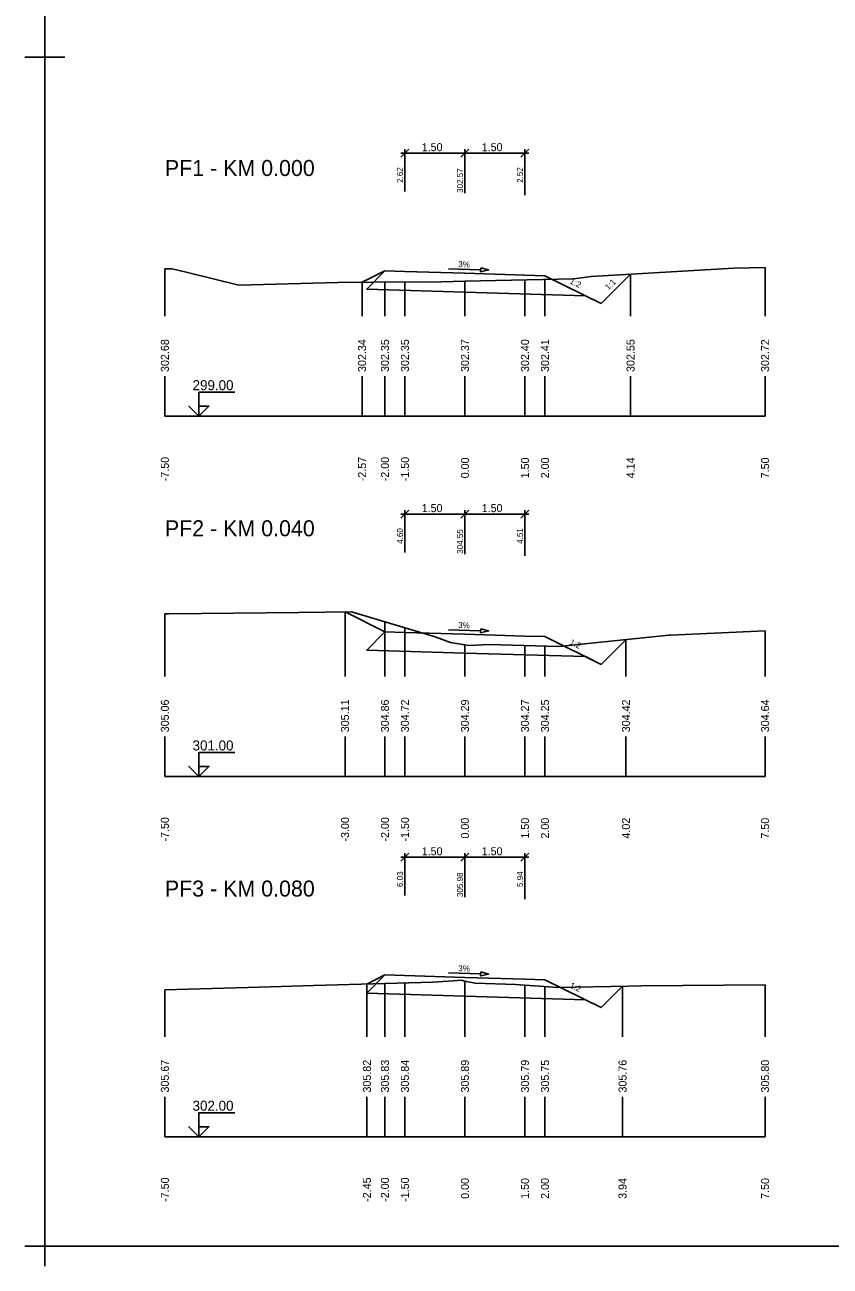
# Model space of a CAD drawing. Extents: x -5 to 1265, y -2 to 602.
# Drawn here: x -5 to 196.3, y -2.3 to 307.8 of the extents above; entities that cross this region are included whole.
import ezdxf

# ---------------------------------------------------------------- set-up
doc = ezdxf.new("R2010")
doc.units = 0
for name, color, linetype in [('KOTA', 7, 'Continuous'), ('KOTA_DELKY', 7, 'Continuous'), ('KOTA_DELKY_CONT', 7, 'Continuous'), ('NS_TELESO_VOZOVKY', 7, 'Continuous'), ('NS_V_PF', 7, 'Continuous'), ('REZY_PF_PUVODNI', 7, 'Continuous'), ('SESTAVY_REZU_PF', 7, 'Continuous'), ('SKLON', 7, 'Continuous'), ('SVK', 7, 'Continuous')]:
    doc.layers.add(name, color=color, linetype=linetype)

msp = doc.modelspace()

# ---------------------------------------------------------------- linework, layer by layer
for p, q in [((0, 304.67), (0, 294.67)), ((0, 304.67), (0, 294.67)), ((0, 304.67), (0, 294.67)), ((0, 304.67), (0, 294.67)), ((0, 304.67), (0, 294.67)), ((0, 304.67), (0, 294.67)), ((0, 304.67), (0, 294.67)), ((0, 304.67), (0, 294.67)), ((0, 304.67), (0, 294.67)), ((0, 304.67), (0, 294.67)), ((0, 304.67), (0, 294.67)), ((0, 304.67), (0, 294.67)), ((0, 304.67), (0, 294.67)), ((0, 304.67), (0, 294.67)), ((0, 304.67), (0, 294.67)), ((0, 304.67), (0, 294.67)), ((0, 304.67), (0, 294.67)), ((0, 304.67), (0, 294.67)), ((0, 304.67), (0, 294.67)), ((0, 304.67), (0, 294.67)), ((0, 304.67), (0, 294.67)), ((0, 304.67), (0, 294.67)), ((0, 304.67), (0, 294.67)), ((0, 304.67), (0, 294.67)), ((0, 304.67), (0, 294.67)), ((0, 304.67), (0, 294.67)), ((0, 304.67), (0, 294.67)), ((0, 304.67), (0, 294.67)), ((0, 304.67), (0, 294.67)), ((0, 304.67), (0, 294.67)), ((0, 304.67), (0, 294.67)), ((0, 304.67), (0, 294.67)), ((0, 304.67), (0, 294.67)), ((0, 304.67), (0, 294.67)), ((0, 304.67), (0, 294.67)), ((0, 304.67), (0, 294.67)), ((0, 304.67), (0, 294.67)), ((0, 304.67), (0, 294.67)), ((0, 304.67), (0, 294.67)), ((0, 304.67), (0, 294.67)), ((0, 304.67), (0, 294.67)), ((0, 304.67), (0, 294.67)), ((0, 304.67), (0, 294.67)), ((0, 304.67), (0, 294.67)), ((5, 299.67), (-5, 299.67)), ((5, 299.67), (-5, 299.67)), ((5, 299.67), (-5, 299.67)), ((5, 299.67), (-5, 299.67)), ((5, 299.67), (-5, 299.67)), ((5, 299.67), (-5, 299.67)), ((5, 299.67), (-5, 299.67)), ((5, 299.67), (-5, 299.67)), ((5, 299.67), (-5, 299.67)), ((5, 299.67), (-5, 299.67)), ((5, 299.67), (-5, 299.67)), ((5, 299.67), (-5, 299.67)), ((5, 299.67), (-5, 299.67)), ((5, 299.67), (-5, 299.67)), ((5, 299.67), (-5, 299.67)), ((5, 299.67), (-5, 299.67)), ((5, 299.67), (-5, 299.67)), ((5, 299.67), (-5, 299.67)), ((5, 299.67), (-5, 299.67)), ((5, 299.67), (-5, 299.67)), ((5, 299.67), (-5, 299.67)), ((5, 299.67), (-5, 299.67)), ((5, 299.67), (-5, 299.67)), ((5, 299.67), (-5, 299.67)), ((5, 299.67), (-5, 299.67)), ((5, 299.67), (-5, 299.67)), ((5, 299.67), (-5, 299.67)), ((5, 299.67), (-5, 299.67)), ((5, 299.67), (-5, 299.67)), ((5, 299.67), (-5, 299.67)), ((5, 299.67), (-5, 299.67)), ((5, 299.67), (-5, 299.67)), ((5, 299.67), (-5, 299.67)), ((5, 299.67), (-5, 299.67)), ((5, 299.67), (-5, 299.67)), ((5, 299.67), (-5, 299.67)), ((5, 299.67), (-5, 299.67)), ((5, 299.67), (-5, 299.67)), ((5, 299.67), (-5, 299.67)), ((5, 299.67), (-5, 299.67)), ((5, 299.67), (-5, 299.67)), ((5, 299.67), (-5, 299.67)), ((5, 299.67), (-5, 299.67)), ((5, 299.67), (-5, 299.67)), ((0, 7.67), (0, -2.33)), ((0, 7.67), (0, -2.33)), ((0, 7.67), (0, -2.33)), ((0, 7.67), (0, -2.33)), ((0, 7.67), (0, -2.33)), ((0, 7.67), (0, -2.33)), ((0, 7.67), (0, -2.33)), ((0, 7.67), (0, -2.33)), ((5, 2.67), (-5, 2.67)), ((5, 2.67), (-5, 2.67)), ((5, 2.67), (-5, 2.67)), ((5, 2.67), (-5, 2.67)), ((5, 2.67), (-5, 2.67)), ((5, 2.67), (-5, 2.67)), ((5, 2.67), (-5, 2.67)), ((5, 2.67), (-5, 2.67))]:
    msp.add_line(p, q)
msp.add_lwpolyline([(0, 596.67), (1260, 596.67), (1260, 2.67), (0, 2.67)], close=True)
at = {"layer": 'KOTA'}
for points in [[(38.51, 210), (36.01, 212.5), (38.51, 210), (38.51, 216), (47.51, 216)], [(38.51, 210), (41.01, 212.5), (38.51, 212.5), (38.51, 210)], [(38.51, 210), (41.01, 212.5), (38.51, 212.5)], [(38.51, 120), (36.01, 122.5), (38.51, 120), (38.51, 126), (47.51, 126)], [(38.51, 120), (41.01, 122.5), (38.51, 122.5), (38.51, 120)], [(38.51, 120), (41.01, 122.5), (38.51, 122.5)], [(38.51, 30), (36.01, 32.5), (38.51, 30), (38.51, 36), (47.51, 36)], [(38.51, 30), (41.01, 32.5), (38.51, 32.5), (38.51, 30)], [(38.51, 30), (41.01, 32.5), (38.51, 32.5)]]:
    msp.add_lwpolyline(points, dxfattribs=at)
at = {"layer": 'KOTA_DELKY'}
for points in [[(89, 274.7), (91, 276.7)], [(90, 266.15), (90, 276.7)], [(104, 274.7), (106, 276.7)], [(104, 274.7), (106, 276.7)], [(105, 265.7), (105, 276.7)], [(105, 265.7), (105, 276.7)], [(119, 274.7), (121, 276.7)], [(120, 265.25), (120, 276.7)], [(89, 275.7), (106, 275.7)], [(104, 275.7), (121, 275.7)], [(89, 184.54), (91, 186.54)], [(90, 175.99), (90, 186.54)], [(104, 184.54), (106, 186.54)], [(104, 184.54), (106, 186.54)], [(105, 175.54), (105, 186.54)], [(105, 175.54), (105, 186.54)], [(119, 184.54), (121, 186.54)], [(120, 175.09), (120, 186.54)], [(89, 185.54), (106, 185.54)], [(104, 185.54), (121, 185.54)], [(89, 98.81), (91, 100.81)], [(89, 99.81), (106, 99.81)], [(90, 90.26), (90, 100.81)], [(104, 98.81), (106, 100.81)], [(104, 98.81), (106, 100.81)], [(104, 99.81), (121, 99.81)], [(105, 89.81), (105, 100.81)], [(105, 89.81), (105, 100.81)], [(119, 98.81), (121, 100.81)], [(120, 89.36), (120, 100.81)]]:
    msp.add_lwpolyline(points, dxfattribs=at)
at = {"layer": 'NS_TELESO_VOZOVKY'}
for points in [[(105, 245.7), (120, 245.25), (125, 245.1), (139.01, 238.17), (135.11, 240.1), (105, 241), (80.44, 241.74), (85, 246.3), (90, 246.15), (105, 245.7)], [(105, 155.54), (120, 155.09), (125, 154.94), (139.01, 148.01), (135.11, 149.94), (105, 150.84), (80.44, 151.58), (85, 156.14), (90, 155.99), (105, 155.54)], [(105, 69.81), (120, 69.36), (125, 69.21), (139.01, 62.27), (135.11, 64.2), (105, 65.11), (80.44, 65.84), (85, 70.41), (90, 70.26), (105, 69.81)]]:
    msp.add_lwpolyline(points, dxfattribs=at)
at = {"layer": 'NS_V_PF'}
for points in [[(79.28, 243.44), (85, 246.3), (90, 246.15), (105, 245.7), (120, 245.25), (125, 245.1), (139.01, 238.17), (146.38, 245.46)], [(75.02, 161.13), (85, 156.14), (90, 155.99), (105, 155.54), (120, 155.09), (125, 154.94), (139.01, 148.01), (145.24, 154.17)], [(80.49, 68.15), (85, 70.41), (90, 70.26), (105, 69.81), (120, 69.36), (125, 69.21), (139.01, 62.27), (144.38, 67.59)]]:
    msp.add_lwpolyline(points, dxfattribs=at)
at = {"layer": 'REZY_PF_PUVODNI'}
for points in [[(30, 246.81), (31.76, 246.8), (33.2, 246.47), (35.63, 245.9), (48.46, 242.76), (73.22, 243.39), (81.88, 243.46), (99.16, 243.57), (105, 243.7), (132.21, 244.31), (136.52, 244.88), (172.17, 246.98), (180, 247.15)], [(30, 160.59), (30.98, 160.61), (63.51, 161), (76.61, 161.15), (97.54, 154.91), (101.42, 153.45), (105, 152.89), (105, 152.89), (106.01, 152.73), (111.08, 152.98), (128.42, 152.43), (155.93, 155.28), (156.34, 155.32), (180, 156.36)], [(30, 66.71), (53.63, 67.4), (67.13, 67.78), (96.93, 68.61), (102.08, 68.97), (104.02, 69.11), (105, 68.9), (105, 68.9), (107.58, 68.33), (117.66, 68.06), (128.18, 67.26), (145.91, 67.62), (149.16, 67.66), (180, 67.99)]]:
    msp.add_lwpolyline(points, dxfattribs=at)
at = {"layer": 'SESTAVY_REZU_PF'}
for points in [[(30, 210), (180, 210)], [(30, 120), (180, 120)], [(30, 30), (180, 30)]]:
    msp.add_lwpolyline(points, dxfattribs=at)
at = {"layer": 'SKLON'}
for points in [[(100.92, 246.82), (108.91, 246.58)], [(108.93, 247.08), (110.91, 246.52), (108.9, 246.08), (108.93, 247.08)], [(100.92, 156.66), (108.91, 156.42)], [(108.93, 156.92), (110.91, 156.36), (108.9, 155.92), (108.93, 156.92)], [(100.92, 70.93), (108.91, 70.69)], [(108.93, 71.19), (110.91, 70.63), (108.9, 70.19), (108.93, 71.19)]]:
    msp.add_lwpolyline(points, dxfattribs=at)
for points in [[(108.93, 247.08), (110.91, 246.52), (108.9, 246.08)], [(108.93, 156.92), (110.91, 156.36), (108.9, 155.92)], [(108.93, 71.19), (110.91, 70.63), (108.9, 70.19)]]:
    msp.add_lwpolyline(points, close=True, dxfattribs=at)
at = {"layer": 'SVK'}
for points in [[(30, 235), (30, 246.81)], [(146.38, 235), (146.38, 245.46)], [(180, 235), (180, 247.15)], [(79.28, 235), (79.28, 243.44)], [(85, 235), (85, 243.48)], [(90, 235), (90, 243.51)], [(105, 235), (105, 243.7)], [(120, 235), (120, 244.04)], [(125, 235), (125, 244.15)], [(30, 210), (30, 220)], [(79.28, 210), (79.28, 220)], [(85, 210), (85, 220)], [(90, 210), (90, 220)], [(105, 210), (105, 220)], [(120, 210), (120, 220)], [(125, 210), (125, 220)], [(146.38, 210), (146.38, 220)], [(180, 210), (180, 220)], [(30, 145), (30, 160.59)], [(75.02, 145), (75.02, 161.13)], [(85, 145), (85, 158.65)], [(90, 145), (90, 157.16)], [(180, 145), (180, 156.36)], [(105, 145), (105, 152.89)], [(120, 145), (120, 152.69)], [(125, 145), (125, 152.54)], [(145.24, 145), (145.24, 154.17)], [(30, 120), (30, 130)], [(75.02, 120), (75.02, 130)], [(85, 120), (85, 130)], [(90, 120), (90, 130)], [(105, 120), (105, 130)], [(120, 120), (120, 130)], [(125, 120), (125, 130)], [(145.24, 120), (145.24, 130)], [(180, 120), (180, 130)], [(85, 55), (85, 68.28)], [(90, 55), (90, 68.42)], [(105, 55), (105, 68.9)], [(30, 55), (30, 66.71)], [(80.49, 55), (80.49, 68.15)], [(120, 55), (120, 67.89)], [(125, 55), (125, 67.51)], [(144.38, 55), (144.38, 67.59)], [(180, 55), (180, 67.99)], [(30, 30), (30, 40)], [(80.49, 30), (80.49, 40)], [(85, 30), (85, 40)], [(90, 30), (90, 40)], [(105, 30), (105, 40)], [(120, 30), (120, 40)], [(125, 30), (125, 40)], [(144.38, 30), (144.38, 40)], [(180, 30), (180, 40)]]:
    msp.add_lwpolyline(points, dxfattribs=at)

# ---------------------------------------------------------------- texts
at = {"layer": 'KOTA'}
for s, p in [('299.00', (36.93, 216.5)), ('301.00', (36.93, 126.5)), ('302.00', (36.93, 36.5))]:
    msp.add_text(s, height=2.5, dxfattribs=at).set_placement(p)
at = {"layer": 'KOTA_DELKY'}
for p in [(94.19, 276.2), (109.19, 276.2), (94.19, 186.04), (109.19, 186.04), (94.19, 100.31), (109.19, 100.31)]:
    msp.add_text('1.50', height=2, dxfattribs=at).set_placement(p)
at = {"layer": 'KOTA_DELKY_CONT'}
for s, p in [('2.62', (89.5, 268.29)), ('302.57', (104.5, 265.78)), ('2.52', (119.5, 268.29)), ('4.60', (89.5, 178.13)), ('304.55', (104.5, 175.62)), ('4.51', (119.5, 178.13)), ('6.03', (89.5, 92.39)), ('5.94', (119.5, 92.39)), ('305.98', (104.5, 89.88))]:
    msp.add_text(s, height=1.5, rotation=90, dxfattribs=at).set_placement(p)
at = {"layer": 'SESTAVY_REZU_PF'}
for s, p in [('PF1 - KM 0.000', (30, 270)), ('PF2 - KM 0.040', (30, 180)), ('PF3 - KM 0.080', (30, 90))]:
    msp.add_text(s, height=4, dxfattribs=at).set_placement(p)
at = {"layer": 'SKLON'}
for s, rotation, p in [('3%', 358.2816, (103.29, 247.25)), ('1:2', 333.679, (131.04, 243.23)), ('1:1', 44.7149, (140.87, 241.41)), ('3%', 358.2816, (103.29, 157.09)), ('1:2', 333.679, (131.04, 153.07)), ('3%', 358.2816, (103.29, 71.36)), ('1:2', 333.679, (131.04, 67.33))]:
    msp.add_text(s, height=1.5, rotation=rotation, dxfattribs=at).set_placement(p)
at = {"layer": 'SVK'}
for s, p in [(' 302.68', (31, 220.3)), (' 302.34', (80.28, 220.3)), (' 302.35', (86, 220.3)), (' 302.35', (91, 220.3)), (' 302.37', (106, 220.3)), (' 302.40', (121, 220.3)), (' 302.41', (126, 220.3)), (' 302.55', (147.38, 220.3)), (' 302.72', (181, 220.3)), (' -7.50', (31, 193)), (' -2.57', (80.28, 193)), (' -2.00', (86, 193)), (' -1.50', (91, 193)), ('  0.00', (106, 193)), ('  1.50', (121, 193)), ('  2.00', (126, 193)), ('  4.14', (147.38, 193)), ('  7.50', (181, 193)), (' 305.06', (31, 130.3)), (' 305.11', (76.02, 130.3)), (' 304.86', (86, 130.3)), (' 304.72', (91, 130.3)), (' 304.29', (106, 130.3)), (' 304.27', (121, 130.3)), (' 304.25', (126, 130.3)), (' 304.42', (146.24, 130.3)), (' 304.64', (181, 130.3)), (' -7.50', (31, 103)), (' -3.00', (76.02, 103)), (' -2.00', (86, 103)), (' -1.50', (91, 103)), ('  0.00', (106, 103)), ('  1.50', (121, 103)), ('  2.00', (126, 103)), ('  4.02', (146.24, 103)), ('  7.50', (181, 103)), (' 305.67', (31, 40.3)), (' 305.82', (81.49, 40.3)), (' 305.83', (86, 40.3)), (' 305.84', (91, 40.3)), (' 305.89', (106, 40.3)), (' 305.79', (121, 40.3)), (' 305.75', (126, 40.3)), (' 305.76', (145.38, 40.3)), (' 305.80', (181, 40.3)), (' -7.50', (31, 13)), (' -2.45', (81.49, 13)), (' -2.00', (86, 13)), (' -1.50', (91, 13)), ('  0.00', (106, 13)), ('  1.50', (121, 13)), ('  2.00', (126, 13)), ('  3.94', (145.38, 13)), ('  7.50', (181, 13))]:
    msp.add_text(s, height=2, rotation=90, dxfattribs=at).set_placement(p)

doc.saveas('drawing.dxf')
